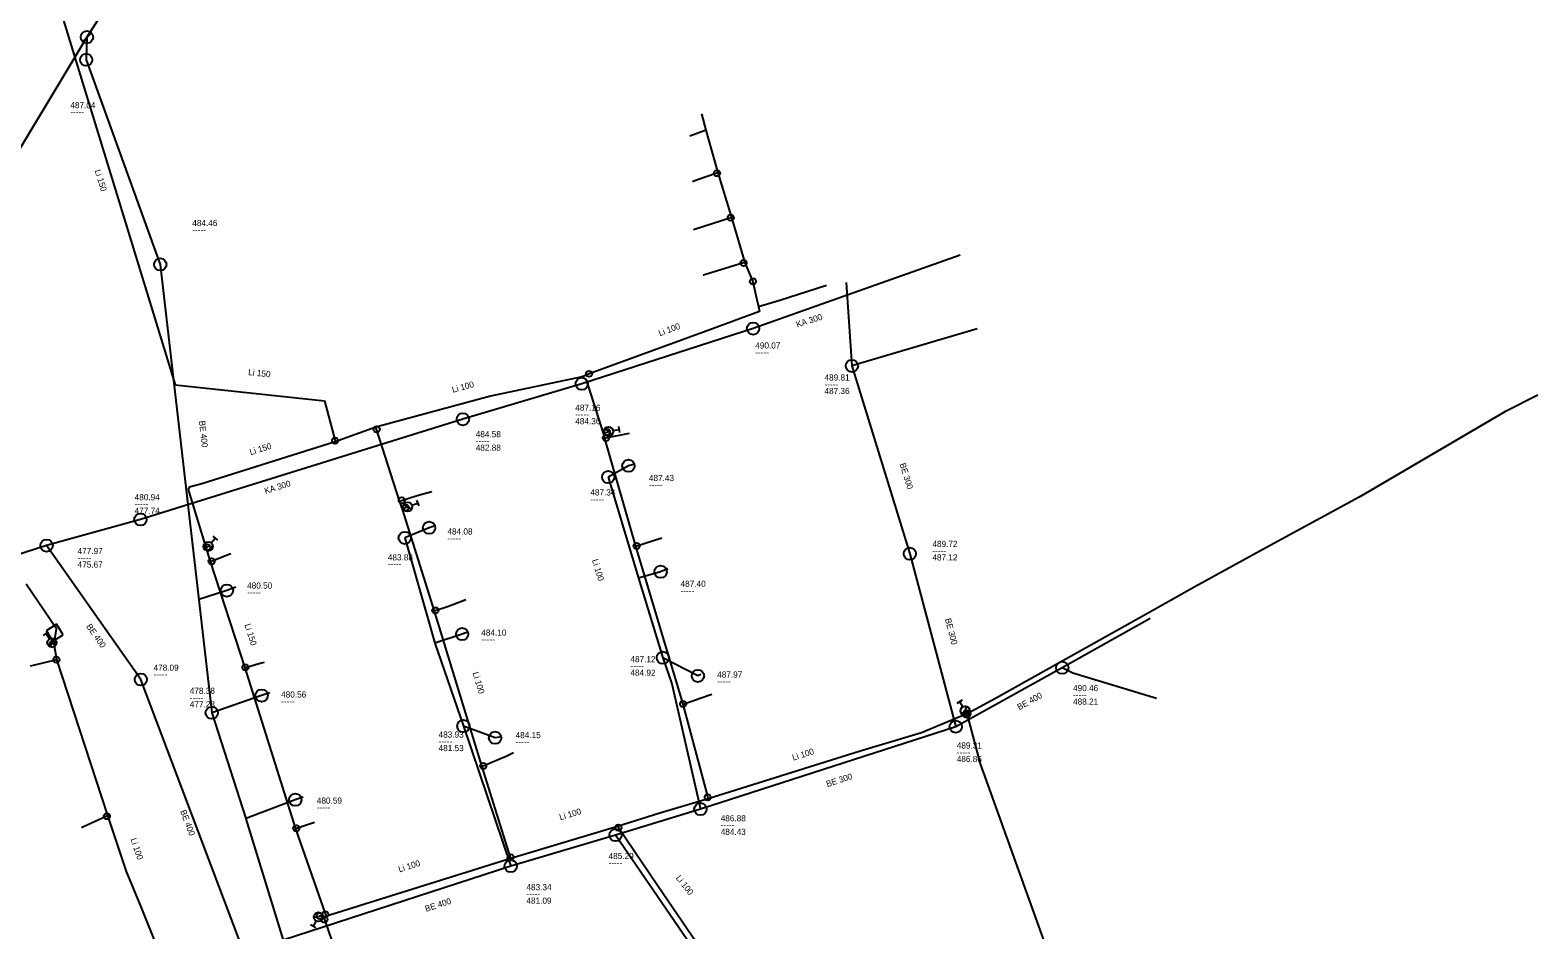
# Model space of a CAD drawing. Extents: x -685576 to -685179, y -1163336 to -1162895.
# Drawn here: x -685424.5 to -685179.1, y -1163211.6 to -1163065.1 of the extents above; entities that cross this region are included whole.
import ezdxf

# ---------------------------------------------------------------- set-up
doc = ezdxf.new("R2010")
doc.units = 0
doc.layers.add('Level 0', color=7, linetype='Continuous')

msp = doc.modelspace()

# ---------------------------------------------------------------- linework, layer by layer
at = {"layer": 'Level 0'}
for p, q in [((-685409.64, -1163057.39), (-685415.3, -1163066.26)), ((-685419.92, -1163060.93), (-685400.96, -1163122.89)), ((-685415.3, -1163066.26), (-685441.48, -1163109.74)), ((-685415.99, -1163066.98), (-685414.58, -1163065.58)), ((-685415.3, -1163066.26), (-685415.43, -1163069.96)), ((-685415.43, -1163069.96), (-685403.36, -1163103.27)), ((-685315.27, -1163078.75), (-685314.54, -1163081.41)), ((-685314.69, -1163081.49), (-685317.18, -1163082.4)), ((-685314.54, -1163081.41), (-685314.69, -1163081.49)), ((-685314.54, -1163081.41), (-685312.6, -1163088.39)), ((-685312.74, -1163088.42), (-685316.06, -1163089.54)), ((-685312.6, -1163088.39), (-685312.74, -1163088.42)), ((-685312.6, -1163088.39), (-685310.37, -1163095.61)), ((-685316.06, -1163089.54), (-685316.72, -1163089.85)), ((-685310.5, -1163095.67), (-685316.54, -1163097.65)), ((-685310.37, -1163095.61), (-685310.5, -1163095.67)), ((-685310.37, -1163095.61), (-685308.22, -1163103)), ((-685403.36, -1163103.27), (-685394.98, -1163176.24)), ((-685308.41, -1163103.03), (-685314.96, -1163105.04)), ((-685308.22, -1163103), (-685308.41, -1163103.03)), ((-685308.22, -1163103), (-685306.9, -1163106.04)), ((-685273.17, -1163101.75), (-685306.86, -1163113.71)), ((-685314.96, -1163105.04), (-685314.97, -1163105.04)), ((-685306.9, -1163106.04), (-685306.34, -1163108.56)), ((-685302.5, -1163109.08), (-685294.91, -1163106.67)), ((-685291.7, -1163106.24), (-685290.78, -1163119.79)), ((-685306.34, -1163108.56), (-685305.98, -1163110.14)), ((-685305.98, -1163110.14), (-685302.5, -1163109.08)), ((-685305.98, -1163110.14), (-685305.8, -1163110.92)), ((-685305.8, -1163110.92), (-685314.52, -1163114.11)), ((-685306.86, -1163113.71), (-685334.76, -1163122.69)), ((-685314.52, -1163114.11), (-685329.98, -1163119.77)), ((-685270.41, -1163113.73), (-685290.78, -1163119.79)), ((-685329.98, -1163119.77), (-685333.56, -1163121.08)), ((-685290.78, -1163119.79), (-685281.35, -1163150.36)), ((-685400.96, -1163122.89), (-685376.64, -1163125.5)), ((-685334.76, -1163122.69), (-685354.1, -1163128.47)), ((-685334.7, -1163121.57), (-685349.62, -1163124.69)), ((-685333.56, -1163121.08), (-685334.7, -1163121.57)), ((-685334.7, -1163121.57), (-685334.04, -1163122.04)), ((-685334.04, -1163122.04), (-685331.29, -1163130.72)), ((-685376.64, -1163125.5), (-685374.9, -1163131.97)), ((-685349.62, -1163124.69), (-685368.26, -1163129.74)), ((-685179.12, -1163124.57), (-685184.51, -1163127.24)), ((-685184.51, -1163127.24), (-685207.2, -1163140.54)), ((-685354.1, -1163128.47), (-685406.6, -1163144.79)), ((-685368.26, -1163129.74), (-685374.88, -1163132.16)), ((-685368.15, -1163130.11), (-685368.26, -1163129.74)), ((-685364.4, -1163141.76), (-685368.15, -1163130.11)), ((-685330.96, -1163129.96), (-685329.84, -1163130.96)), ((-685329.66, -1163130.33), (-685328.68, -1163130.16)), ((-685328.76, -1163129.66), (-685328.59, -1163130.65)), ((-685374.88, -1163132.16), (-685396.59, -1163139)), ((-685374.9, -1163131.97), (-685374.88, -1163132.16)), ((-685331.29, -1163130.72), (-685330.67, -1163130.55)), ((-685331.29, -1163130.72), (-685331.05, -1163131.59)), ((-685331.05, -1163131.59), (-685330.83, -1163131.52)), ((-685331.05, -1163131.59), (-685325.99, -1163149.15)), ((-685330.83, -1163131.52), (-685327, -1163130.75)), ((-685330.67, -1163130.55), (-685330.4, -1163130.46)), ((-685327.15, -1163136.05), (-685330.45, -1163137.88)), ((-685326.13, -1163135.81), (-685327.15, -1163136.05)), ((-685398.64, -1163139.54), (-685398.85, -1163139.88)), ((-685398.85, -1163139.88), (-685395.95, -1163149.36)), ((-685396.59, -1163139), (-685398.64, -1163139.54)), ((-685361.55, -1163140.89), (-685359.16, -1163140.23)), ((-685330.45, -1163137.88), (-685325.54, -1163154.34)), ((-685364.4, -1163141.76), (-685364.26, -1163141.74)), ((-685363.95, -1163143.1), (-685364.4, -1163141.76)), ((-685364.26, -1163141.74), (-685361.55, -1163140.89)), ((-685363.74, -1163142.33), (-685362.46, -1163143.12)), ((-685362.4, -1163142.46), (-685361.46, -1163142.12)), ((-685361.63, -1163141.65), (-685361.28, -1163142.59)), ((-685208.19, -1163141.13), (-685222.67, -1163149.03)), ((-685207.2, -1163140.54), (-685208.19, -1163141.13)), ((-685406.6, -1163144.79), (-685421.86, -1163149.04)), ((-685363.95, -1163143.1), (-685363.42, -1163142.86)), ((-685358.72, -1163159.71), (-685363.95, -1163143.1)), ((-685363.42, -1163142.86), (-685363.1, -1163142.72)), ((-685394.82, -1163147.51), (-685394.05, -1163148.15)), ((-685359.6, -1163146.12), (-685363.56, -1163147.79)), ((-685358.61, -1163145.83), (-685359.6, -1163146.12)), ((-685421.86, -1163149.04), (-685427.1, -1163150.7)), ((-685406.53, -1163170.83), (-685421.86, -1163149.04)), ((-685396.31, -1163149.15), (-685394.81, -1163149.2)), ((-685395.95, -1163149.36), (-685395.71, -1163149.31)), ((-685395.95, -1163149.35), (-685395.95, -1163149.36)), ((-685395.95, -1163149.36), (-685395.25, -1163151.62)), ((-685395.71, -1163149.31), (-685395.56, -1163149.17)), ((-685395.08, -1163148.6), (-685394.44, -1163147.83)), ((-685363.56, -1163147.79), (-685360.04, -1163160.15)), ((-685325.99, -1163149.15), (-685325.81, -1163149.08)), ((-685325.99, -1163149.15), (-685318.32, -1163174.84)), ((-685325.81, -1163149.08), (-685321.71, -1163147.77)), ((-685222.67, -1163149.03), (-685234.98, -1163155.74)), ((-685395.25, -1163151.62), (-685395.01, -1163151.58)), ((-685395.25, -1163151.62), (-685389.58, -1163168.91)), ((-685395.01, -1163151.58), (-685392.48, -1163150.56)), ((-685392.48, -1163150.56), (-685391.9, -1163150.32)), ((-685281.35, -1163150.36), (-685273.88, -1163178.51)), ((-685321.91, -1163153.29), (-685325.54, -1163154.34)), ((-685325.54, -1163154.34), (-685321.55, -1163167.28)), ((-685320.73, -1163152.84), (-685321.91, -1163153.29)), ((-685420.25, -1163162.58), (-685425.17, -1163155.33)), ((-685392.52, -1163156.37), (-685397.1, -1163157.8)), ((-685391.04, -1163155.81), (-685392.52, -1163156.37)), ((-685234.98, -1163155.74), (-685242.64, -1163160.11)), ((-685358.72, -1163159.71), (-685358.6, -1163159.6)), ((-685351.04, -1163184.9), (-685358.72, -1163159.71)), ((-685358.6, -1163159.6), (-685356.45, -1163158.89)), ((-685356.45, -1163158.89), (-685353.62, -1163157.83)), ((-685420.24, -1163161.85), (-685421.93, -1163162.92)), ((-685419.17, -1163163.54), (-685420.24, -1163161.85)), ((-685360.04, -1163160.15), (-685358.69, -1163164.9)), ((-685242.64, -1163160.11), (-685267.43, -1163173.95)), ((-685242.23, -1163160.93), (-685256.54, -1163168.91)), ((-685422.38, -1163163.65), (-685421.55, -1163163.09)), ((-685421.41, -1163164.2), (-685421.96, -1163163.37)), ((-685421.93, -1163162.92), (-685420.86, -1163164.61)), ((-685421.24, -1163165.54), (-685420.76, -1163164.12)), ((-685420.86, -1163164.61), (-685419.17, -1163163.54)), ((-685420.65, -1163165.07), (-685420.25, -1163162.58)), ((-685354.22, -1163163.45), (-685358.69, -1163164.9)), ((-685353.2, -1163163.08), (-685354.22, -1163163.45)), ((-685420.88, -1163165.07), (-685421, -1163164.83)), ((-685420.65, -1163165.07), (-685420.88, -1163165.07)), ((-685420.19, -1163167.58), (-685420.65, -1163165.07)), ((-685358.69, -1163164.9), (-685354.03, -1163178.41)), ((-685424.07, -1163168.53), (-685424.53, -1163168.64)), ((-685420.26, -1163167.61), (-685424.07, -1163168.53)), ((-685420.19, -1163167.58), (-685420.26, -1163167.61)), ((-685411.88, -1163192.98), (-685420.19, -1163167.58)), ((-685389.58, -1163168.91), (-685389.5, -1163168.87)), ((-685389.58, -1163168.91), (-685381.37, -1163195.13)), ((-685389.5, -1163168.87), (-685387.08, -1163168.19)), ((-685387.08, -1163168.19), (-685386.38, -1163167.99)), ((-685321.55, -1163167.28), (-685320.09, -1163171.52)), ((-685315.85, -1163170.24), (-685321.55, -1163167.28)), ((-685256.54, -1163168.91), (-685273.88, -1163178.51)), ((-685254.84, -1163169.79), (-685256.54, -1163168.91)), ((-685390.47, -1163213.33), (-685406.53, -1163170.83)), ((-685320.09, -1163171.52), (-685315.45, -1163191.93)), ((-685315.38, -1163170.02), (-685315.85, -1163170.24)), ((-685241.19, -1163173.93), (-685254.84, -1163169.79)), ((-685386.86, -1163173.46), (-685394.98, -1163176.24)), ((-685385.53, -1163172.98), (-685386.86, -1163173.46)), ((-685318.25, -1163174.84), (-685314.06, -1163173.39)), ((-685314.06, -1163173.39), (-685313.57, -1163173.23)), ((-685273.65, -1163174.66), (-685272.78, -1163174.16)), ((-685272.71, -1163175.28), (-685273.21, -1163174.41)), ((-685267.43, -1163173.95), (-685271.99, -1163176.41)), ((-685394.98, -1163176.24), (-685389.46, -1163193.48)), ((-685318.32, -1163174.84), (-685318.25, -1163174.84)), ((-685318.32, -1163174.84), (-685314.24, -1163190.02)), ((-685272.2, -1163176.49), (-685279.46, -1163179.53)), ((-685272.62, -1163176.62), (-685272.06, -1163175.23)), ((-685272.17, -1163176.33), (-685272.34, -1163175.93)), ((-685272.11, -1163176.45), (-685272.2, -1163176.49)), ((-685272.11, -1163176.45), (-685272.17, -1163176.33)), ((-685271.99, -1163176.41), (-685272.11, -1163176.45)), ((-685272.11, -1163176.45), (-685272.03, -1163176.58)), ((-685272.03, -1163176.58), (-685269.88, -1163184.54)), ((-685354.03, -1163178.41), (-685346.32, -1163201.19)), ((-685348.87, -1163180.31), (-685354.03, -1163178.41)), ((-685273.88, -1163178.51), (-685315.45, -1163191.93)), ((-685347.77, -1163180.15), (-685348.87, -1163180.31)), ((-685279.46, -1163179.53), (-685289.58, -1163182.54)), ((-685350.8, -1163184.89), (-685346.94, -1163183.25)), ((-685346.94, -1163183.25), (-685345.84, -1163182.74)), ((-685289.58, -1163182.54), (-685314.18, -1163190.28)), ((-685351.04, -1163184.9), (-685350.8, -1163184.89)), ((-685346.35, -1163199.78), (-685351.04, -1163184.9)), ((-685269.88, -1163184.54), (-685249.32, -1163241.89)), ((-685381.38, -1163190.4), (-685389.55, -1163193.52)), ((-685380.09, -1163189.97), (-685381.38, -1163190.4)), ((-685314.18, -1163190.28), (-685322.05, -1163192.61)), ((-685314.24, -1163190.02), (-685314.18, -1163190.28)), ((-685412.05, -1163193.09), (-685415.85, -1163194.8)), ((-685411.88, -1163192.98), (-685412.05, -1163193.09)), ((-685408.85, -1163202.11), (-685411.88, -1163192.98)), ((-685389.46, -1163193.48), (-685389.45, -1163193.49)), ((-685389.45, -1163193.49), (-685383.34, -1163213.24)), ((-685381.21, -1163195.04), (-685378.26, -1163194.07)), ((-685315.45, -1163191.93), (-685329.26, -1163196.15)), ((-685322.05, -1163192.61), (-685328.91, -1163194.76)), ((-685415.85, -1163194.8), (-685416.16, -1163194.95)), ((-685381.37, -1163195.13), (-685381.21, -1163195.04)), ((-685381.37, -1163195.13), (-685376.48, -1163209.06)), ((-685329.26, -1163196.15), (-685346.32, -1163201.19)), ((-685328.91, -1163194.76), (-685346.31, -1163199.95)), ((-685309.45, -1163225.05), (-685329.26, -1163196.15)), ((-685328.8, -1163194.96), (-685328.91, -1163194.76)), ((-685322.31, -1163204.53), (-685328.8, -1163194.96)), ((-685346.32, -1163201.19), (-685383.34, -1163213.24)), ((-685346.31, -1163199.95), (-685376.33, -1163209.36)), ((-685346.31, -1163199.95), (-685346.35, -1163199.78)), ((-685406.47, -1163207.84), (-685408.85, -1163202.11)), ((-685311.11, -1163220.95), (-685322.31, -1163204.53)), ((-685403.73, -1163214.71), (-685406.47, -1163207.84)), ((-685378.06, -1163211.25), (-685378.93, -1163210.75)), ((-685377.99, -1163210.13), (-685378.49, -1163211)), ((-685376.88, -1163209.37), (-685378.36, -1163209.59)), ((-685377.4, -1163209.32), (-685377.62, -1163209.48)), ((-685377.17, -1163209.28), (-685377.4, -1163209.32)), ((-685376.72, -1163209.55), (-685377.17, -1163209.28)), ((-685376.33, -1163209.36), (-685376.72, -1163209.55)), ((-685376.72, -1163209.55), (-685376.64, -1163209.9)), ((-685376.64, -1163209.9), (-685374.03, -1163217.52)), ((-685376.48, -1163209.06), (-685376.33, -1163209.36))]:
    msp.add_line(p, q, dxfattribs=at)
for centre, radius in [((-685415.3, -1163066.26), 1), ((-685415.43, -1163069.96), 1), ((-685312.74, -1163088.42), 0.5), ((-685310.5, -1163095.67), 0.5), ((-685403.36, -1163103.27), 1), ((-685308.41, -1163103.03), 0.5), ((-685306.9, -1163106.04), 0.5), ((-685306.86, -1163113.71), 1), ((-685333.56, -1163121.08), 0.5), ((-685290.78, -1163119.79), 1), ((-685334.76, -1163122.69), 1), ((-685354.1, -1163128.47), 1), ((-685368.15, -1163130.11), 0.5), ((-685330.67, -1163130.55), 0.5), ((-685330.4, -1163130.46), 0.75), ((-685374.9, -1163131.97), 0.5), ((-685330.83, -1163131.52), 0.5), ((-685327.15, -1163136.05), 1), ((-685330.45, -1163137.88), 1), ((-685364.05, -1163141.67), 0.5), ((-685363.42, -1163142.86), 0.5), ((-685363.1, -1163142.72), 0.75), ((-685406.6, -1163144.79), 1), ((-685359.6, -1163146.12), 1), ((-685363.56, -1163147.79), 1), ((-685421.86, -1163149.04), 1), ((-685395.56, -1163149.17), 0.75), ((-685395.71, -1163149.31), 0.5), ((-685325.81, -1163149.08), 0.5), ((-685281.35, -1163150.36), 1), ((-685395.01, -1163151.58), 0.5), ((-685321.91, -1163153.29), 1), ((-685392.52, -1163156.37), 1), ((-685358.6, -1163159.6), 0.5), ((-685421, -1163164.83), 0.75), ((-685420.88, -1163165.07), 0.5), ((-685354.22, -1163163.45), 1), ((-685420.26, -1163167.61), 0.5), ((-685321.55, -1163167.28), 1), ((-685389.5, -1163168.87), 0.5), ((-685315.85, -1163170.24), 1), ((-685256.54, -1163168.91), 1), ((-685406.53, -1163170.83), 1), ((-685386.86, -1163173.46), 1), ((-685318.25, -1163174.84), 0.5), ((-685394.98, -1163176.24), 1), ((-685272.34, -1163175.93), 0.75), ((-685272.2, -1163176.49), 0.5), ((-685272.17, -1163176.33), 0.5), ((-685272.03, -1163176.58), 0.5), ((-685271.99, -1163176.41), 0.5), ((-685354.03, -1163178.41), 1), ((-685348.87, -1163180.31), 1), ((-685273.88, -1163178.51), 1), ((-685350.8, -1163184.89), 0.5), ((-685381.38, -1163190.4), 1), ((-685315.45, -1163191.93), 1), ((-685314.24, -1163190.02), 0.5), ((-685412.05, -1163193.09), 0.5), ((-685381.21, -1163195.04), 0.5), ((-685329.26, -1163196.15), 1), ((-685328.8, -1163194.96), 0.5), ((-685346.32, -1163201.19), 1), ((-685346.35, -1163199.78), 0.5), ((-685377.62, -1163209.48), 0.75), ((-685377.4, -1163209.32), 0.5), ((-685376.48, -1163209.06), 0.5), ((-685376.64, -1163209.9), 0.5)]:
    msp.add_circle(centre, radius, dxfattribs=at)

# ---------------------------------------------------------------- texts
for s, p in [('487.04', (-685418, -1163077.85)), ('-----', (-685418, -1163078.95)), ('484.46', (-685398.15, -1163097.02)), ('-----', (-685398.15, -1163098.12)), ('490.07', (-685306.51, -1163116.96)), ('-----', (-685306.51, -1163118.06)), ('489.81', (-685295.24, -1163122.17)), ('-----', (-685295.24, -1163123.27)), ('487.36', (-685295.24, -1163124.37)), ('487.16', (-685335.81, -1163127.09)), ('-----', (-685335.81, -1163128.19)), ('484.58', (-685352.01, -1163131.4)), ('484.36', (-685335.81, -1163129.29)), ('482.88', (-685352.01, -1163133.6)), ('-----', (-685352.01, -1163132.5)), ('487.43', (-685323.82, -1163138.53)), ('487.34', (-685333.36, -1163140.88)), ('-----', (-685323.82, -1163139.63)), ('480.94', (-685407.54, -1163141.66)), ('-----', (-685407.54, -1163142.76)), ('-----', (-685333.36, -1163141.98)), ('477.74', (-685407.54, -1163143.86)), ('484.08', (-685356.62, -1163147.24)), ('477.97', (-685416.82, -1163150.41)), ('-----', (-685356.62, -1163148.34)), ('489.72', (-685277.68, -1163149.26)), ('-----', (-685277.68, -1163150.36)), ('475.67', (-685416.82, -1163152.61)), ('-----', (-685416.82, -1163151.51)), ('483.88', (-685366.32, -1163151.45)), ('-----', (-685366.32, -1163152.55)), ('487.12', (-685277.68, -1163151.46)), ('487.40', (-685318.67, -1163155.75)), ('480.50', (-685389.22, -1163156.04)), ('-----', (-685389.22, -1163157.14)), ('-----', (-685318.67, -1163156.85)), ('484.10', (-685351.11, -1163163.7)), ('-----', (-685351.11, -1163164.8)), ('487.12', (-685326.83, -1163168.02)), ('478.09', (-685404.46, -1163169.41)), ('484.92', (-685326.83, -1163170.22)), ('-----', (-685326.83, -1163169.12)), ('487.97', (-685312.71, -1163170.53)), ('-----', (-685404.46, -1163170.51)), ('-----', (-685312.71, -1163171.63)), ('490.46', (-685254.78, -1163172.73)), ('478.38', (-685398.56, -1163173.17)), ('477.28', (-685398.56, -1163175.37)), ('-----', (-685398.56, -1163174.27)), ('480.56', (-685383.69, -1163173.77)), ('-----', (-685383.69, -1163174.87)), ('488.21', (-685254.78, -1163174.93)), ('-----', (-685254.78, -1163173.83)), ('483.93', (-685358.06, -1163180.29)), ('484.15', (-685345.52, -1163180.38)), ('481.53', (-685358.06, -1163182.49)), ('-----', (-685358.06, -1163181.39)), ('-----', (-685345.52, -1163181.48)), ('489.31', (-685273.71, -1163182.07)), ('486.86', (-685273.71, -1163184.27)), ('-----', (-685273.71, -1163183.17)), ('480.59', (-685377.88, -1163191.04)), ('-----', (-685377.88, -1163192.14)), ('486.88', (-685312.14, -1163193.92)), ('484.43', (-685312.14, -1163196.12)), ('-----', (-685312.14, -1163195.02)), ('485.29', (-685330.39, -1163200.06)), ('-----', (-685330.39, -1163201.16)), ('483.34', (-685343.76, -1163205.13)), ('481.09', (-685343.76, -1163207.33)), ('-----', (-685343.76, -1163206.23))]:
    msp.add_text(s, height=1, dxfattribs=at).set_placement(p)
for s, rotation, p in [('Li 150', 287.015, (-685414.05, -1163088)), ('Li 100', 20.108, (-685322.05, -1163114.97)), ('KA 300', 17.841, (-685299.67, -1163113.56)), ('Li 150', 353.88, (-685389.09, -1163121.28)), ('Li 100', 15.159, (-685355.73, -1163124.17)), ('BE 400', 276.551, (-685397.07, -1163128.76)), ('Li 150', 17.488, (-685388.64, -1163134.33)), ('BE 300', 287.144, (-685283.02, -1163135.77)), ('KA 300', 17.268, (-685386.24, -1163140.64)), ('Li 100', 286.624, (-685333.09, -1163151.4)), ('BE 400', 305.128, (-685415.47, -1163162.21)), ('Li 150', 287.386, (-685389.67, -1163161.93)), ('BE 300', 284.862, (-685275.65, -1163161.02)), ('Li 100', 286.956, (-685352.55, -1163169.77)), ('BE 400', 28.97, (-685263.53, -1163175.85)), ('Li 100', 17.465, (-685300.32, -1163184.05)), ('BE 300', 17.892, (-685294.78, -1163188.35)), ('BE 400', 290.701, (-685400.14, -1163192.28)), ('Li 100', 16.609, (-685338.24, -1163193.75)), ('Li 100', 288.36, (-685408.21, -1163196.82)), ('Li 100', 17.404, (-685364.43, -1163202.23)), ('Li 100', 308.047, (-685319.5, -1163203.16)), ('BE 400', 18.03, (-685360.08, -1163208.66))]:
    msp.add_text(s, height=1, rotation=rotation, dxfattribs=at).set_placement(p)

doc.saveas('drawing.dxf')
